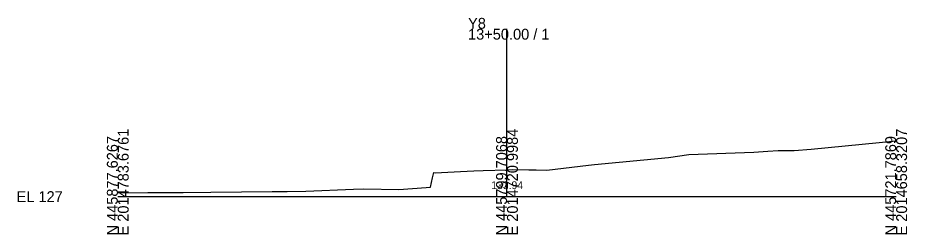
# Model space of a CAD drawing. Extents: x -26 to 1403, y -10 to 8043.
# Drawn here: x -25.7 to 202.8, y 6990.3 to 7046.1 of the extents above; entities that cross this region are included whole.
import ezdxf

# ---------------------------------------------------------------- set-up
doc = ezdxf.new("R2010")
doc.units = 0
for name, color, linetype in [('Default', 7, 'Continuous'), ('Exist Cross Section Cell', 7, 'Continuous'), ('Exist XS Center Line Elevation Label', 7, 'Continuous'), ('Exist XS Ground Line', 7, 'Continuous')]:
    doc.layers.add(name, color=color, linetype=linetype)

msp = doc.modelspace()

# ---------------------------------------------------------------- linework, layer by layer
at = {"layer": 'Exist Cross Section Cell'}
for p, q in [((100, 7000), (100, 7043.23)), ((0, 7000), (100, 7000)), ((100, 7000), (200, 7000))]:
    msp.add_line(p, q, dxfattribs=at)
at = {"layer": 'Exist XS Ground Line'}
msp.add_lwpolyline([(0, 7000.95), (7.71, 7001.05), (9.68, 7001.05), (11.26, 7001.05), (16.79, 7001.06), (23.9, 7001.11), (39.63, 7001.34), (43.51, 7001.34), (48.36, 7001.37), (60.58, 7001.93), (63.23, 7001.98), (72.2, 7001.8), (79.27, 7002.34), (80.32, 7002.45), (80.86, 7004.85), (81.23, 7006.22), (81.52, 7006.13), (88.07, 7006.44), (91.52, 7006.6), (93.88, 7006.69), (100, 7006.94), (101.35, 7006.99), (105.66, 7006.92), (107.51, 7006.87), (110.21, 7006.82), (120.95, 7008.08), (122.49, 7008.26), (141.47, 7010.04), (146.7, 7010.83), (163.41, 7011.47), (167.01, 7011.7), (169.64, 7011.85), (173.82, 7011.85), (178.13, 7012.19), (200, 7014.41)], dxfattribs=at)

# ---------------------------------------------------------------- texts
at = {"layer": 'Default'}
msp.add_text('-', height=0.0001, dxfattribs=at).set_placement((0, 7000))
at = {"layer": 'Exist Cross Section Cell'}
for s, p in [('Y8', (90, 7043.23)), ('13+50.00 / 1', (90, 7040.43)), ('EL 127', (-26, 6998.6))]:
    msp.add_text(s, height=2.8, dxfattribs=at).set_placement(p)
for s, p in [('E 2014783.6761', (2.8, 6990)), ('E 2014720.9984', (102.8, 6990)), ('E 2014658.3207', (202.8, 6990)), ('N 445877.6267', (0, 6990)), ('N 445799.7068', (100, 6990)), ('N 445721.7869', (200, 6990))]:
    msp.add_text(s, height=2.8, rotation=90, dxfattribs=at).set_placement(p)
at = {"layer": 'Exist XS Center Line Elevation Label'}
msp.add_text('133.94', height=2, dxfattribs=at).set_placement((95.96, 7001.94))

doc.saveas('drawing.dxf')
